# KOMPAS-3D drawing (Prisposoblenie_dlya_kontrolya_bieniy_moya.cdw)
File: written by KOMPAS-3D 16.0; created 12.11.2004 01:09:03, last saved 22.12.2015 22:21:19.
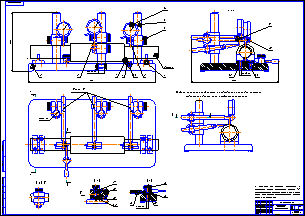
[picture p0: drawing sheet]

Sheet 1: A0, landscape

Title block, sheet 1: name: Приспособление / контрольное / Сборочный чертеж; scale: 1:2; sheets: 1; organisation: СПбГПУ / гр. В 43321/1; sheet format: A0; stored path: D:\11 семестр(ДИПЛОМ)\ДИПЛОМ МОЙ\Приспособление для контроля биений.cdw; drawn by: Емельянов; checked by: Колышкин

Views: Вид Г
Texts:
  Js13
  Рабочее положение индикатора и подводимого упора для контроля
  радиального биения наружной поверхности вала
  Риски "Р"
  1. Положения для контроля радиального и
  торцевого биения маркированы рисками "Р"
  соответственно. Высота знаков - 5мм, марки-
  ровку производить виброкарандашом (ширина
  риски - не более 0.5мм).
Dimensions and other numbers on the sheet: 230; 500; 1; 2; 3; 5; 24; 6; 22; 8; 345; 20; 18; 25; 23; 10; 9; 4; 16; 15; 14; 13; 17; 7; 19; 30; 1:2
